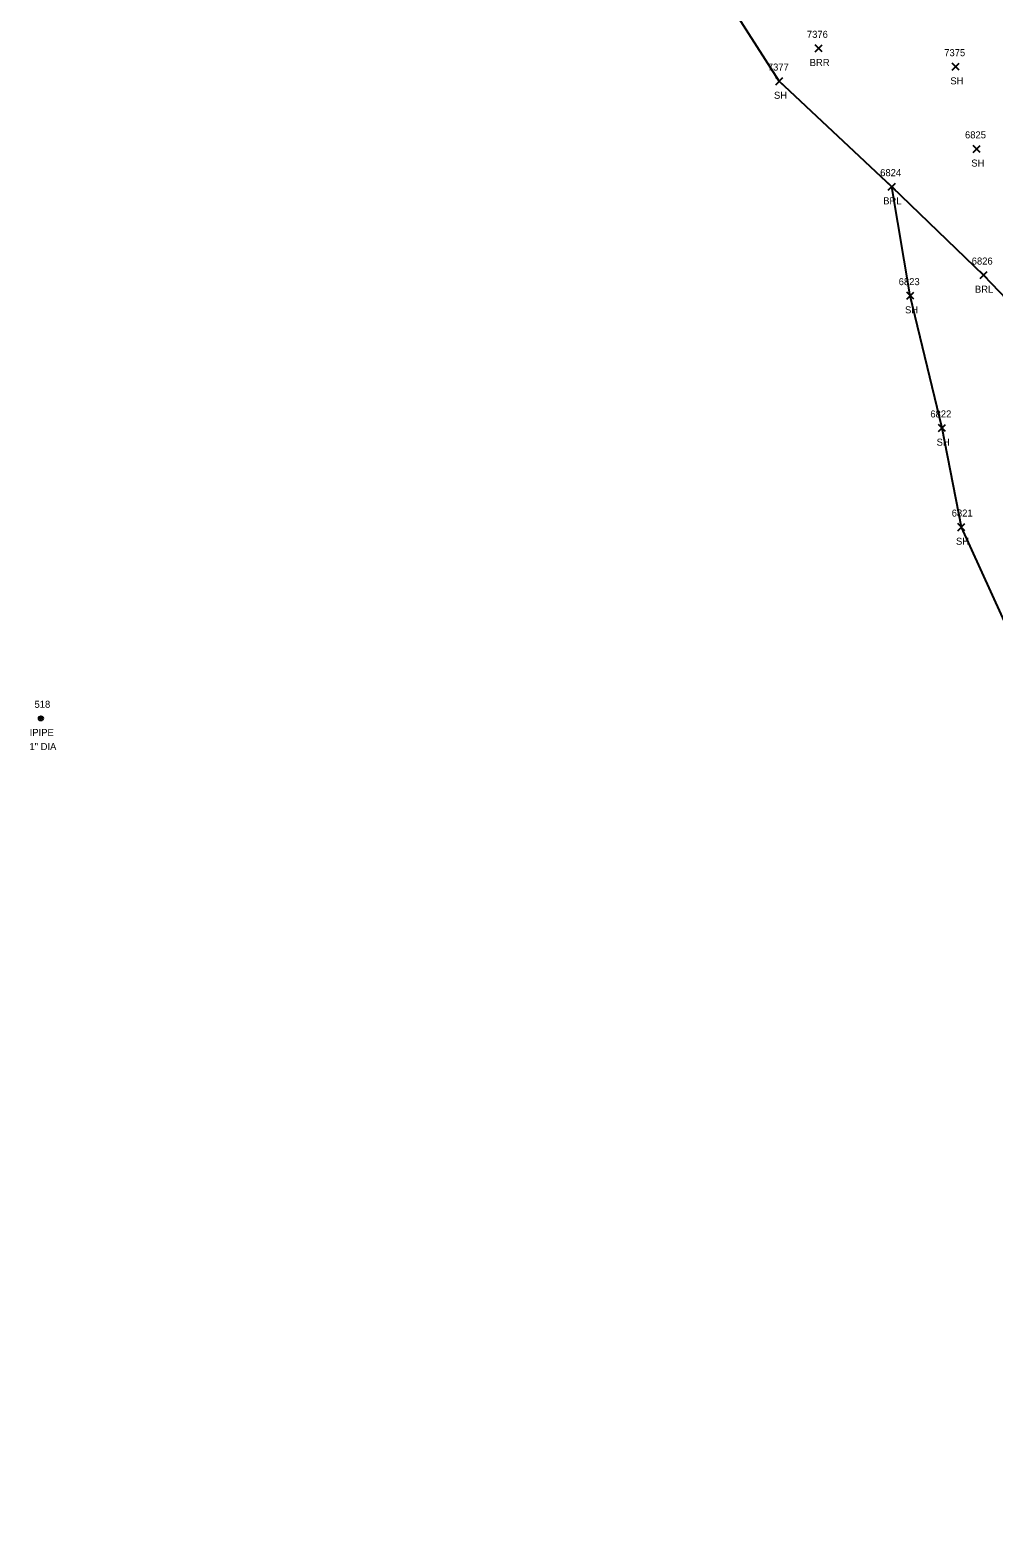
# Model space of a CAD drawing. Extents: x 1439173 to 1457902, y 641926 to 659889.
# Drawn here: x 1448374.4 to 1448647.9, y 643615.4 to 644043.5 of the extents above; entities that cross this region are included whole.
import ezdxf

# ---------------------------------------------------------------- set-up
doc = ezdxf.new("R2010")
doc.units = 0
for name, color, linetype in [('L_A', 7, 'Continuous'), ('L_I', 7, 'Continuous'), ('L_TIC', 7, 'Continuous'), ('LABL', 7, 'Continuous'), ('LSOGP', 7, 'Continuous'), ('M_A', 7, 'Continuous'), ('M_C', 7, 'Continuous'), ('M_I', 7, 'Continuous'), ('MPIP', 7, 'Continuous')]:
    doc.layers.add(name, color=color, linetype=linetype)

msp = doc.modelspace()

# ---------------------------------------------------------------- linework, layer by layer
at = {"layer": 'L_TIC'}
for points in [[(1448597.13, 644037.31), (1448599.13, 644039.31)], [(1448599.13, 644037.31), (1448597.13, 644039.31)], [(1448636.04, 644032.1), (1448638.04, 644034.1)], [(1448638.04, 644032.1), (1448636.04, 644034.1)], [(1448585.99, 644028.01), (1448587.99, 644030.01)], [(1448587.99, 644028.01), (1448585.99, 644030.01)], [(1448641.97, 644008.76), (1448643.97, 644010.76)], [(1448643.97, 644008.76), (1448641.97, 644010.76)], [(1448617.91, 643998.04), (1448619.91, 644000.04)], [(1448619.91, 643998.04), (1448617.91, 644000.04)], [(1448643.94, 643972.94), (1448645.94, 643974.94)], [(1448645.94, 643972.94), (1448643.94, 643974.94)], [(1448623.17, 643967.1), (1448625.17, 643969.1)], [(1448625.17, 643967.1), (1448623.17, 643969.1)], [(1448632.14, 643929.53), (1448634.14, 643931.53)], [(1448634.14, 643929.53), (1448632.14, 643931.53)], [(1448637.64, 643901.39), (1448639.64, 643903.39)], [(1448639.64, 643901.39), (1448637.64, 643903.39)]]:
    msp.add_lwpolyline(points, dxfattribs=at)
at = {"layer": 'LABL'}
msp.add_lwpolyline([(1448618.91, 643999.04), (1448644.94, 643973.94), (1448671.1, 643946.56), (1448682.2, 643948.42), (1448702.89, 643955.83), (1448725.89, 643971.95), (1448704.02, 644009.69), (1448685.63, 644054.93), (1448678.87, 644058.56), (1448673.61, 644064.34), (1448671.51, 644072.78), (1448669.91, 644077.81), (1448660.49, 644089.37), (1448661.4, 644110.27), (1448649.96, 644144.44), (1448645.2, 644141.49), (1448627.15, 644134.63), (1448610.9, 644113.33), (1448584.06, 644096.62)], dxfattribs=at)
at = {"layer": 'LSOGP'}
msp.add_lwpolyline([(1448781.37, 643588.62), (1448769.44, 643619.4), (1448757.15, 643636.65), (1448739.02, 643640.02), (1448737.89, 643639.82), (1448735.44, 643638.14), (1448734.46, 643638.08), (1448726.59, 643633.05), (1448720.88, 643665.89), (1448721.81, 643679.51), (1448713.76, 643699.28), (1448696.64, 643739.78), (1448683.17, 643756.83), (1448664.73, 643788.02), (1448663.97, 643817.84), (1448664.8, 643844.85), (1448655.77, 643864.77), (1448638.64, 643902.39), (1448633.15, 643930.53), (1448624.16, 643968.11), (1448618.91, 643999.04), (1448586.99, 644029.02), (1448568.22, 644058.32)], dxfattribs=at)
at = {"layer": 'MPIP'}
for radius in [0.625, 0.0833]:
    msp.add_circle((1448377.46, 643848.1), radius, dxfattribs=at)

# ---------------------------------------------------------------- texts
at = {"layer": 'L_A'}
for s, p in [('BRR', (1448595.61, 644033.31)), ('SH', (1448585.48, 644024.01)), ('SH', (1448635.52, 644028.1)), ('SH', (1448641.46, 644004.76)), ('BRL', (1448616.46, 643994.04)), ('BRL', (1448642.49, 643968.94)), ('SH', (1448622.66, 643963.1)), ('SH', (1448631.63, 643925.53)), ('SH', (1448637.12, 643897.39))]:
    msp.add_text(s, height=2, dxfattribs=at).set_placement(p)
at = {"layer": 'L_I'}
for s, p in [('7376', (1448594.81, 644041.31)), ('7375', (1448633.78, 644036.1)), ('7377', (1448583.73, 644032.01)), ('6825', (1448639.67, 644012.76)), ('6824', (1448615.61, 644002.04)), ('6826', (1448641.58, 643976.94)), ('6823', (1448620.86, 643971.1)), ('6822', (1448629.84, 643933.53)), ('6821', (1448635.9, 643905.39))]:
    msp.add_text(s, height=2, dxfattribs=at).set_placement(p)
at = {"layer": 'M_A'}
msp.add_text('IPIPE', height=2, dxfattribs=at).set_placement((1448374.29, 643843.1))
at = {"layer": 'M_C'}
msp.add_text('1" DIA', height=2, dxfattribs=at).set_placement((1448374.22, 643839.1))
at = {"layer": 'M_I'}
msp.add_text('518', height=2, dxfattribs=at).set_placement((1448375.66, 643851.1))

doc.saveas('drawing.dxf')
